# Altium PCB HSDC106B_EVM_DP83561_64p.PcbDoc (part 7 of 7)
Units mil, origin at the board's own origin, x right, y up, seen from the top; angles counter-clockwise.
Board outline 8750.24 x 6394.7 mil, 6 copper layers (Top Layer, GND1, SIG1, SIG2, GND2, Bottom Layer), stack 60.4 mil thick; 472 components, 324 nets, 1622 pads, 1086 vias.
Unrouted connection lines stored in the file: 1.
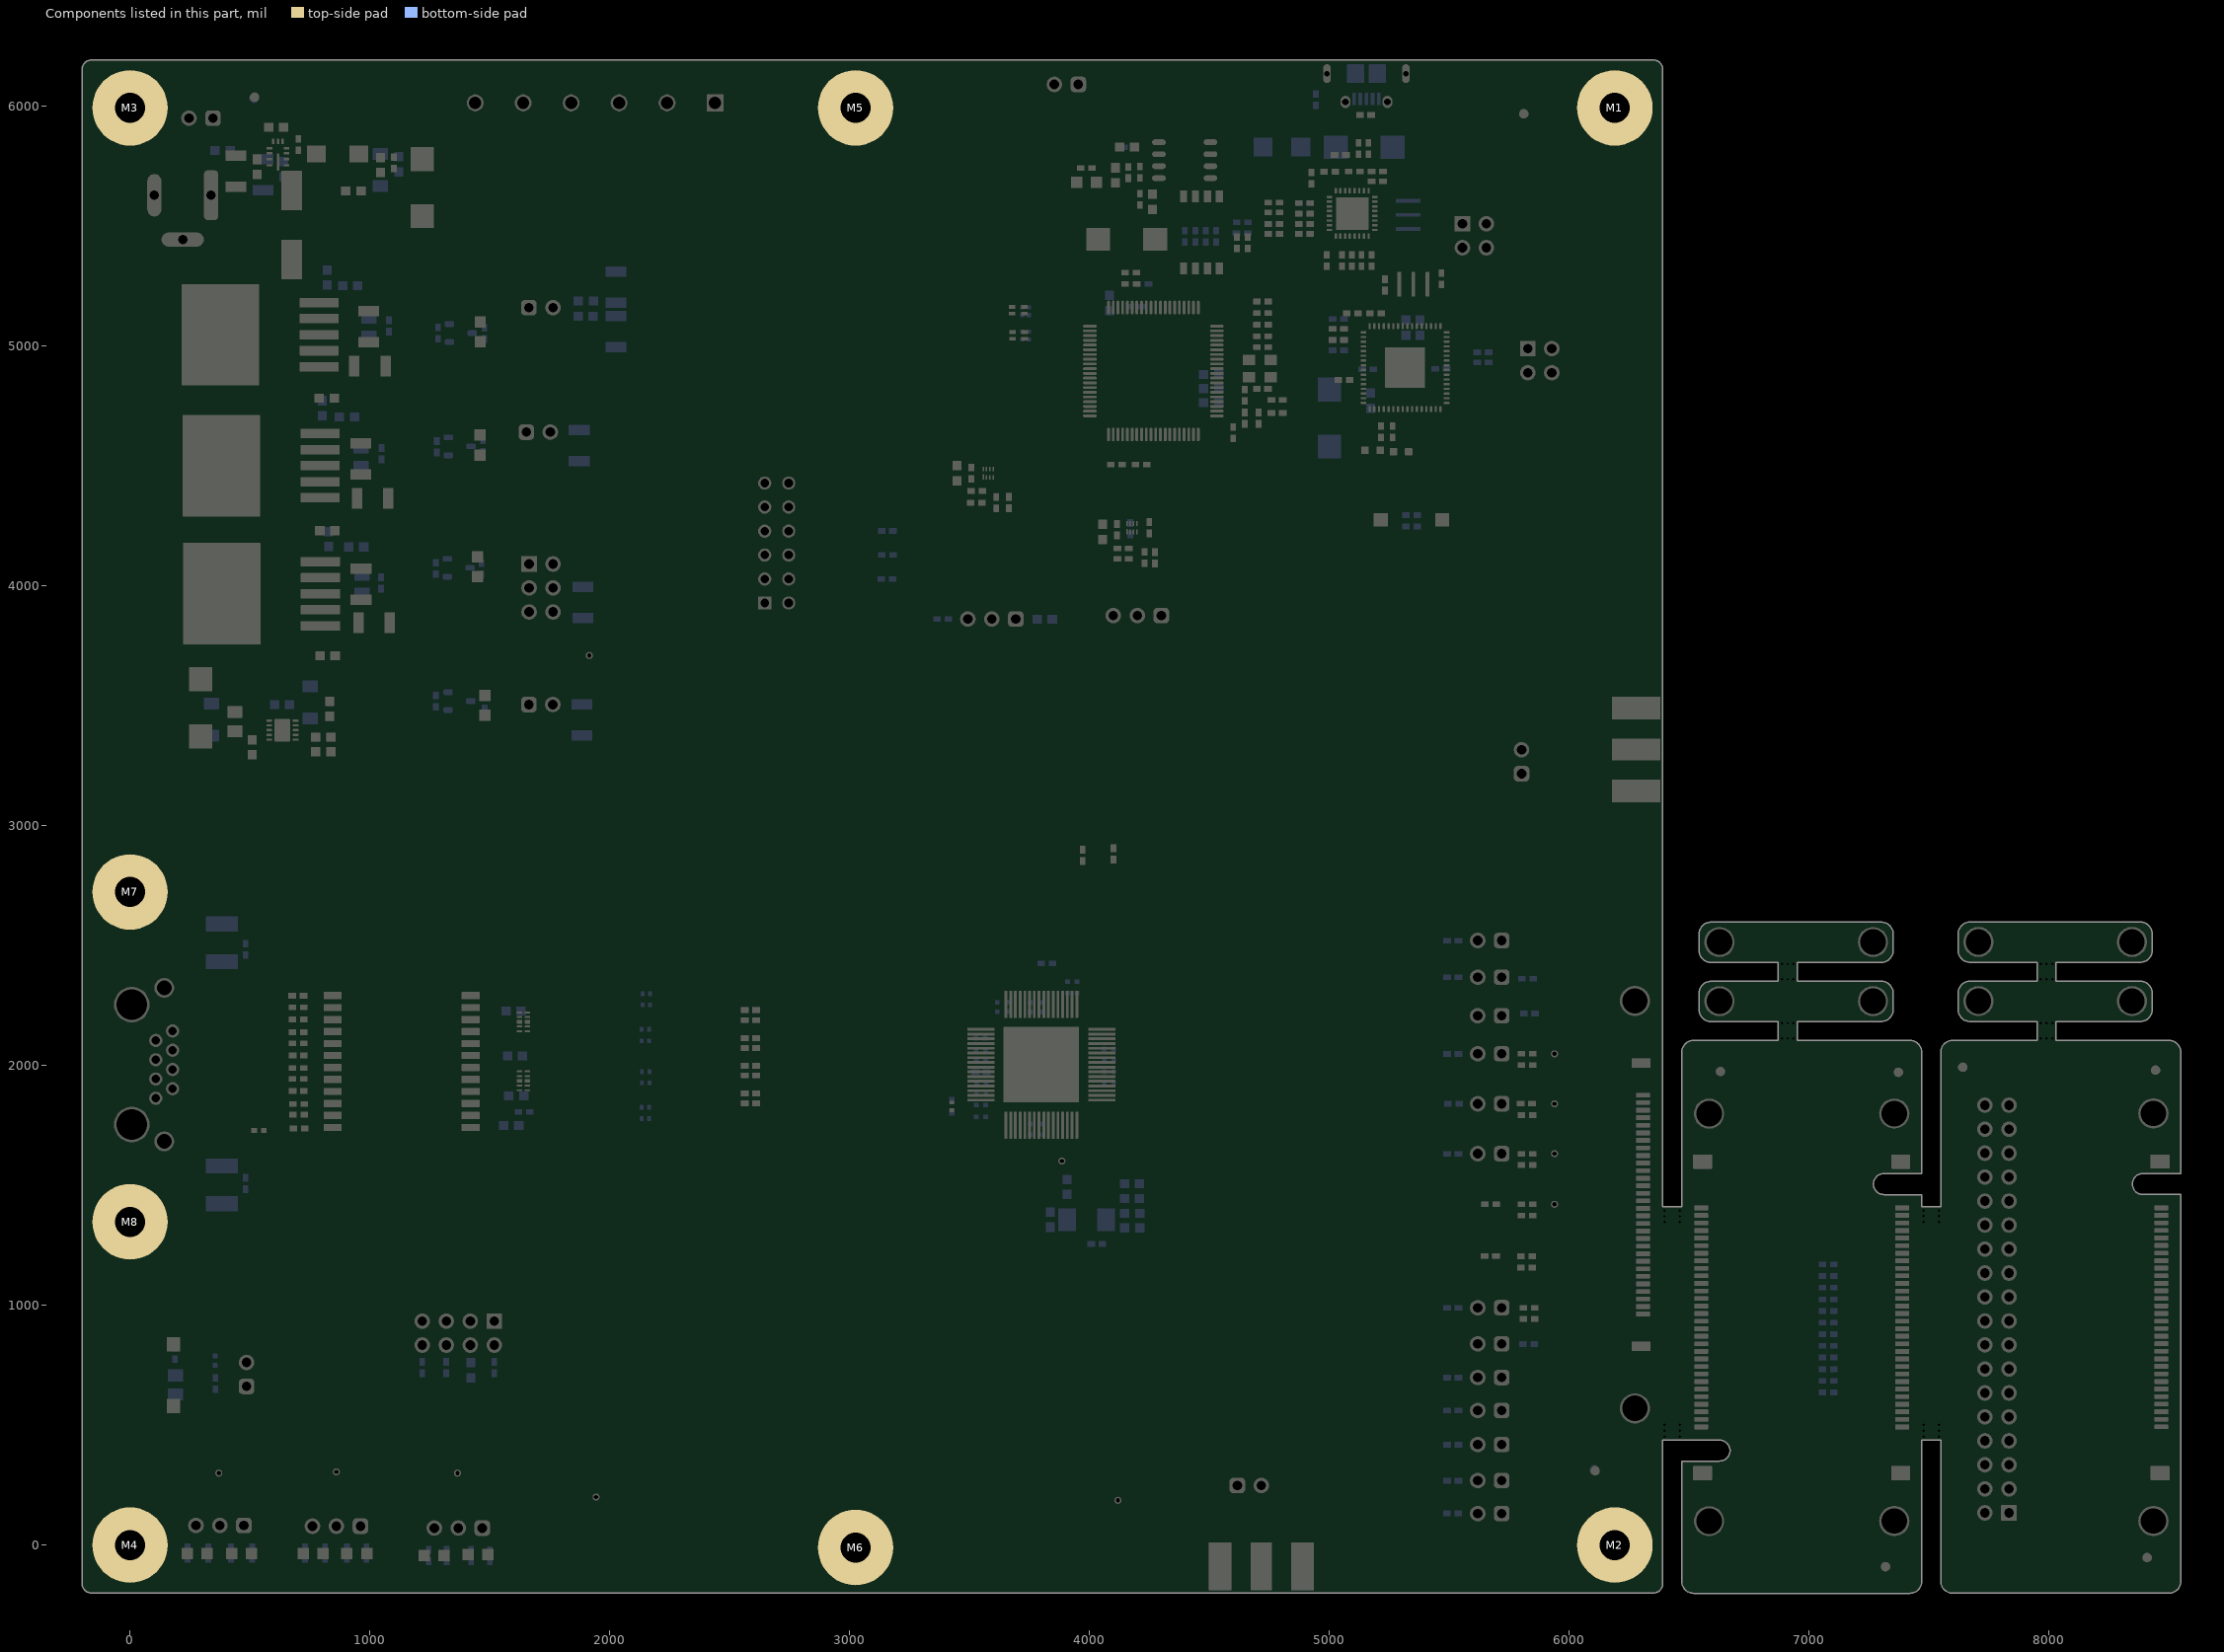
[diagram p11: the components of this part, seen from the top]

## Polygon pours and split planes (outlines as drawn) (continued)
VDDA2P5 on SIG2 "Bottom Layer-No Net" (solid, remove dead copper, pour order 795): 1990,5696.7 1844,5550.7 1844,4378.7 1820,4353.7 1528,4353.7 1492,4389.7 1492,5682.7 1706,5896.7 1706,6118.7 1721,6133.7 1972,6133.7 1990,6115.7
USB_VBUS on SIG2 "Bottom Layer-No Net" (solid, remove dead copper, pour order 798): 30 vertices, not listed, extent 3924,4404.7 6121.52,6171.7
GND_2 on SIG2 "GND_2" (solid, remove dead copper, pour order 821): 27 vertices, not listed, extent 6502,-169 7453,2087
RJ45_ERTH on SIG2 "Bottom Layer-No Net" (solid, remove dead copper, pour order 824): -160,1186.2 -115.4,1141.61 111.6,1141.61 187.6,1217.61 187.6,1490.61 213.6,1517.35 480.62,1517.35 529,1565.73 529,1621.64 529,2418.64 485.36,2462.28 -110.72,2462.28 -160,2413
GND_1 on SIG2 "GND_2" (solid, remove dead copper, pour order 817): 17 vertices, not listed, extent 7582,-160 8512,2066
VDDIO on SIG2 "Bottom Layer-No Net" (solid, pour order 789): 17 vertices, not listed, extent 982,3762.96 1823.64,6134.7
VDDA1P8_AB on SIG2 "Bottom Layer-No Net" (solid, remove dead copper, pour order 801): 17 vertices, not listed, extent 2678.8,1748.74 3639.99,5115.17
VDD1P0 on SIG2 "Bottom Layer-No Net" (solid, remove dead copper, pour order 796): 20 vertices, not listed, extent 1726,3382.2 2337.17,6138.7
VDDA2P5 on SIG2 "Bottom Layer-No Net" (solid, remove dead copper, pour order 799): 19 vertices, not listed, extent 2375.83,1889.05 3465.35,4561.03
1V8 on SIG1 "Bottom Layer-No Net" (solid, pour order 790): 19 vertices, not listed, extent 946.61,4043.7 1922,5306.7
VDD1P0 on SIG1 "VDD1P0_L03_P802" (solid, remove dead copper, pour order 802): 22 vertices, not listed, extent 1728.77,1914.64 4279,3546.97
OC_N on SIG1 "Bottom Layer-No Net" (solid, remove dead copper, pour order 797): 4908,5349.7 4908,5616.7 4919.5,5631.2 4932,5643.7 4992,5643.7 5016,5619.7 5016,5467.7 5036,5447.7 5131,5447.7 5144.81,5433.89 5144.81,5366.51 5099,5320.7 4937,5320.7
GND_2 on SIG1 "GND_2" (solid, remove dead copper, pour order 820): 27 vertices, not listed, extent 6502,-169 7453,2087
RJ45_ERTH on SIG1 "Bottom Layer-No Net" (solid, remove dead copper, pour order 825): -160,1186.2 -115.4,1141.61 111.6,1141.61 187.6,1217.61 187.6,1490.61 213.6,1517.35 480.62,1517.35 529,1565.73 529,1621.64 529,2418.64 485.36,2462.28 -110.72,2462.28 -160,2413
GND_1 on SIG1 "GND_2" (solid, remove dead copper, pour order 816): 17 vertices, not listed, extent 7582,-160 8512,2066
5V on SIG1 "Bottom Layer-No Net" (solid, pour order 793): 25 vertices, not listed, extent -169,3262.7 3895,6138.7
GND on SIG1 "Bottom Layer-No Net" (solid, remove dead copper, pour order 794): 5409,6174.7 5448,6135.7 5448,5757.7 5428,5737.7 4086,5737.7 4073,5750.7 4073,6168.7 4079,6174.7
1V1 on SIG1 "Bottom Layer-No Net" (solid, pour order 792): 852,3567.7 1361,3567.7 1394,3534.7 1693,3534.7 1701,3526.7 1701,3363.7 1689,3351.7 848,3351.7 839,3360.7 839,3554.7
3V3 on SIG1 "Bottom Layer-No Net" (solid, pour order 791): 17 vertices, not listed, extent 991,3592.7 1714,5110.7
GND on GND1 "GND_L02_P837" (solid, remove dead copper, pour order 837): 22 vertices, not listed, extent -160,-150.65 6359,6157.78
GND_2 on GND1 "GND_2" (solid, remove dead copper, pour order 819): 27 vertices, not listed, extent 6502,-169 7453,2087
RJ45_ERTH on GND1 "Bottom Layer-No Net" (solid, remove dead copper, pour order 826): -160,1186.2 -115.4,1141.61 111.6,1141.61 187.6,1217.61 187.6,1490.61 213.6,1517.35 480.62,1517.35 529,1565.73 529,1621.64 529,2418.64 485.36,2462.28 -110.72,2462.28 -160,2413
GND_1 on GND1 "GND_2" (solid, remove dead copper, pour order 815): 17 vertices, not listed, extent 7582,-160 8512,2066
GND on GND2 "GND_L05_P836" (solid, remove dead copper, pour order 836): 22 vertices, not listed, extent -160,-150.65 6359,6157.78
GND_2 on GND2 "GND_2" (solid, remove dead copper, pour order 822): 27 vertices, not listed, extent 6502,-169 7453,2087
RJ45_ERTH on GND2 "Bottom Layer-No Net" (solid, remove dead copper, pour order 823): -160,1186.2 -115.4,1141.61 111.6,1141.61 187.6,1217.61 187.6,1490.61 213.6,1517.35 480.62,1517.35 529,1565.73 529,1621.64 529,2418.64 485.36,2462.28 -110.72,2462.28 -160,2413
GND_1 on GND2 "GND_2" (solid, remove dead copper, pour order 818): 17 vertices, not listed, extent 7582,-160 8512,2066

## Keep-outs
Top Layer:
  circle w10: c5811,5969 r42.8
  circle w10: c6108.36,310.06 r42.8
  circle w10: c519,6038.7 r42.8
Keep-Out Layer:
  text ".Layer_Name" at 397,-2173.3 h60

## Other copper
Top Layer:
  pour cut-out: 3713.06,1326.61 3928.07,1326.61 ccw(c3928.07,1405.13) 3983.6,1349.61 3839.23,1493.98 ccw(c3784.6,1439.35) 3784.6,1516.61 3716.91,1516.61 cw(c3716.91,1543.92) 3697.6,1524.61
  pour cut-out: 1771.36,2180.29 1764.25,2173.17 1764.25,2154.8 1793.91,2125.14 1797.71,2128.93 1797.71,2180.29 1789.06,2188.94
  pour cut-out: 4141.65,4584.91 4196.09,4584.91 4217,4564 4217,4349.97 4282,4284.97 4282,4217 4334,4165 4334,3966 4262,3894 4262,3856 4230,3824 4230,3114 4158,3042 4158,2985.59 4138,2965.59 4138,2722 3877.73,2461.73 3868.46,2461.73 3818,2512.19 3818,2905 4068,3155 4068,3907.4 4162.25,4001.65 4162.25,4278.75 4139,4302 4139,4455 4111,4483 4111,4554.26
  pour cut-out: 4677,309 4747.68,309 4766.6,290.08 4766.6,214.74 4766.6,47.4 4795,19 4795,-180 4781,-194 4651,-194 4638,-181 4638,26 4668.71,56.71 4668.71,277 4668.71,300.71
  pour cut-out: 3323.84,2190.41 3345.4,2168.85 3345.4,2006.15 3359.95,1991.61 3366.82,1991.61 3366.82,2174.48 3357.6,2183.7
  pour cut-out: 5050,5773.7 5101,5773.7 5107,5767.7 5107,5708.05 5099.65,5700.7 5048,5700.7 5040,5708.7 5040,5763.7
  pour cut-out: 809.11,1671 1453.08,1671 1453.08,2366.7 809.11,2366.7
  pour cut-out: 1307.65,4563.7 1562.61,4563.31 1572,4572.7 1572,4645.7 1549,4668.7 1335,4668.7 1303,4636.7 1303,4567.48
  pour cut-out: 1269,5071.31 1291.61,5048.7 1551,5048.7 1575,5072.7 1575,5084.35 1508.67,5150.67 1421.97,5150.67 1420,5148.7 1335,5148.7 1269,5082.7
  pour cut-out: 4658,4730.7 4692,4730.7 4694,4728.7 4694,4653.7 4692,4651.7 4661.88,4651.7 4661.13,4652.46 4661.13,4706.57 4656,4711.7 4656,4728.7
  pour cut-out: 5025.09,5093.39 5024.27,5094.2 5002.5,5094.2 4994.97,5101.73 4994.97,5121.54 5048.76,5121.54 5048.76,5174.43 5063.56,5189.24 5182.15,5189.24 5195,5176.39 5195,5077.7 5188.25,5070.95 5037.75,5070.95 5025.09,5083.61
  pour cut-out: 5195,5121.11 5231.41,5121.11 5234,5123.7 5234,5151.7 5233.3,5152.4 5233.3,5167 5252.7,5167 5267.29,5152.41 5267.29,5099.99 5263,5095.7 5199,5095.7 5195,5099.7
  pour cut-out: 5070.42,4905.7 5062,4905.7 5053,4896.7 5053,4797.7 5058,4792.7 5096.39,4792.7 5097.59,4793.9 5097.59,4807.55 5107.75,4817.7 5125,4817.7 5128,4820.7 5128,4913.39 5120.15,4921.24 5081.4,4921.24 5070.42,4910.26
  pour cut-out: 5052,5627.7 5164.02,5627.7 5166.81,5624.91 5166.81,5561.18 5177.26,5550.73 5198.41,5550.73 5205.48,5543.66 5205.48,5515.18 5201,5510.7 5172.44,5510.7 5169.96,5508.23 5169.96,5484.61 5167.07,5481.71 5025.93,5481.71 5025.93,5622.34 5023.36,5624.91 5026.15,5627.7 5040,5627.7 5040,5634.37 5038.38,5635.99 5024.29,5635.99 5014,5625.7 5014,5480.7 5025,5469.7 5179.21,5469.7 5179.21,5493.61 5189.9,5504.29 5212.59,5504.29 5217,5508.7 5217,5550.7 5204.35,5563.35 5189.9,5563.35 5177.89,5575.35 5177.89,5589.81 5172.86,5589.86
  pour cut-out: 4922.09,5444.74 4922.09,5376.03 4923.63,5374.49 4961.21,5374.49 4986.21,5349.49 5205.83,5349.49 5206.83,5350.49 5206.83,5397.49 5227.83,5418.49 5227.83,5447.49 5203.77,5471.55 5179.11,5471.55 5166.36,5458.8 5024.34,5458.8 5024.34,5458.98 5006.83,5476.49 4953.83,5476.49
  region net VDD1P0: 3909.23,2370.53 3931.19,2370.53 3965.01,2404.35 3965.01,2411.94 3952.86,2424.09 3935.3,2424.09 3902.6,2391.39 3902.6,2377.16
  region net VDDA2P5: 3403.02,1952.01 3446.02,1952.01 3457.32,1940.7 3457.32,1934.57 3450.67,1927.92 3405.03,1927.92 3398.25,1934.7 3398.25,1947.24
  region net VDD1P0: 3411.25,2031.01 3456.02,2031.01 3467.32,2019.7 3467.32,2013.57 3460.67,2006.92 3409.62,2006.92 3403.86,2012.68 3403.86,2023.62
  region net VDDA2P5: 3426.3,2082.22 3434.89,2082.22 3449.47,2096.8 3406.71,2139.56 3397.3,2139.56 3387.82,2130.07 3387.82,2120.38
  pour cut-out: 2858.29,3250.71 3561,2548 3821.9,2548 3951.01,2677.11 3942.03,2686.09 3942.03,2992.82 3829.99,3104.86 3149.95,3784.9 3149.95,4001 2806,4351 2806,4490 2670.95,4490 2573.73,4490 2573.73,3858.47 2858.29,3859.5
  pour cut-out: 3388.85,2385.97 3570.74,2567.86 3580.58,2567.86 3597.83,2550.61 3470.56,2423.34 3470.56,2239.69 3431.16,2200.3 3388.85,2242.61
  pour cut-out: 3613.6,2192.09 3613.6,1817.84 3986.64,1817.84 3986.64,2188.61
  text ".Layer_Name" at 480,-2173.79 h60
GND1:
  pour cut-out: 804.45,1672 1454.36,1672 1454.36,2369 804.45,2369
  text ".Layer_Name" at 480,-2173.79 h60
SIG1:
  pour cut-out: 804.45,1672 1454.12,1672 1454.12,2368 804.45,2368
  text ".Layer_Name" at 480,-2173.79 h60
SIG2:
  pour cut-out: 799,1724 1460.36,1724 1460.36,2319 799,2319
  pour cut-out: 804,1671 1462.84,1671 1462.84,2371 804,2371
  text ".Layer_Name" at 480,-2173.79 h60
GND2:
  pour cut-out: 807,1671 1460.36,1671 1460.36,2368 807,2368
  text ".Layer_Name" at 480,-2173.79 h60
Bottom Layer:
  pour cut-out: 2714,4263 3151,4263 3151,3995.44 3150.44,3996 2714,3996
  pour cut-out: 3150,4243
  pour cut-out: 4748.59,2703.59 5408,3363 6375,3363 6380,3358 6380,3280 6373,3273 5406,3273 4845,2712 4845,2706.59 4848,2703.59 5675.62,2703.59 6134.17,2245.03 6262,2117.2 6262,1046 5830.28,614.28 5830.28,238.54 5737.74,146 4911,146 3792,1265 3792,1471.07 3949.63,1628.69 3949.63,1940.12 3966.64,1957.13 3966.64,2193.54 3927.2,2232.98 3927.2,2402.4 4048.15,2523.36 4529.58,2523.36 4709.81,2703.59
  pour cut-out: 5215,5478.15 5258.85,5522 5386.15,5522 5400,5508.15 5400,5465 5390,5455 5272.17,5455 5261.42,5444.25 5220.9,5444.25 5215,5450.15
  pour cut-out: 5215,5597 5256,5638 5391,5638 5400,5629 5400,5587.59 5387.41,5575 5273.32,5575 5261.42,5563.1 5220.9,5563.1 5215,5569
  pour cut-out: 2103.23,2321.42
  pour cut-out: 3381.6,2170.61 3381.6,1942.46 3428.45,1895.61 3585.6,1895.61 3593.6,1903.61 3593.6,1942.92 3550.6,1985.92 3550.6,2059.61 3524.6,2085.61 3524.6,2171.01 3519,2176.61 3388.6,2176.61 3382.6,2170.61
  pour cut-out: 1222.69,5.97 1222.69,-127.39 1478.6,-127.39 1478.6,23.98
  pour cut-out: 442.6,46.98 219.11,46.98 219.11,-114.39 389.52,-114.39 389.52,15.97 398.69,15.97
  pour cut-out: 707.69,15.97 707.69,-114.39 922.6,-114.39 922.6,18.61
  pour cut-out: 476,3434.7 476,3337.7 480,3333.7 549.84,3333.7 578.84,3362.7 593,3362.7 598,3367.7 598,3384.7 591,3391.7 591,3468.7 578.62,3481.08 521.38,3481.08 475,3434.7
  pour cut-out: 1376,4166.7 1381,4161.7 1381,4066.7 1374,4059.7 1318,4059.7 1297,4080.7 1297,4159.2 1304.5,4166.7
  pour cut-out: 1331,4673.7 1377,4673.7 1389,4661.7 1389,4579.7 1370,4560.7 1370,4559.7 1319.24,4559.7 1317.62,4558.08 1309,4566.7 1309,4660.7 1321,4672.7 1331,4672.7
  pour cut-out: 1330,5148.7 1382,5148.7 1391,5139.7 1391,5043.7 1382,5034.7 1321,5034.7 1307,5048.7 1307,5131.54 1327.18,5151.72
  pour cut-out: 1454.36,2369 806,2369 806,1671 1454.36,1671
  pour cut-out: 4331.37,2758.63 4164,2926 4041.95,2926 3986,2981.95 3986,3014 4021,3049 4371,3049 4787.17,2632.83 5866.17,2632.83 6244,2255 6244,1005 6024.6,785.6 5706.07,785.6 5701.35,784.73 5667.06,819.02 5085.52,819.02 4402.35,1502.2 4055.84,1502.2 4033.17,1524.87 4033.17,1678.05 4033.17,1787.17 4140,1894 4409,1894 4460.42,1945.42 4460.42,2036.44 4448.56,2048.3 4400.63,2048.3 4400.63,2035.17 4346.26,1980.8 4331.37,1995.69
  text ".Layer_Name" at 558,-2173.79 h60

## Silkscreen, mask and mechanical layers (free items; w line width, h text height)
Top Overlay:
  drawing of 165 lines, arcs and shapes, not listed
  text "USB_VBUS" at 4020,6074 h60
  text "5V" at 3720,6070 h40
  text "GND" at 189.97,6022.65 h40
  text "5V" at 335.97,6016.65 h40
  text "5V" at 2471.6,5737.61 h40 r90
  text "GND" at 1465,5713 h40 r90
  text "VDD1P1" at 2240.6,5626.61 h40 r90
  text "VDDIO" at 1672.6,5622.61 h40 r90
  text "EZFET_RST" at 5493,5579 h30
  text "VDDA1P8" at 2035.6,5575.61 h40 r90
  text "VDDA2P5" at 1860.6,5550.7 h40 r90
  text "5V" at 408,5547 h40
  text "GND" at 5724.97,5487.96 h40
  text "GND" at 5722,5386 h40
  text "EZFET_TST" at 5505,5306.61 h30
  text "MSP_TST" at 5758,5063 h40
  text "1V8" at 1574,5050 h40
  text "VDDA1P8" at 1719.6,5045.61 h40
  text "1V8" at 61,5034 h40
  text "GND" at 6003.78,4962.25 h40
  text "GND" at 6009.78,4857.25 h40
  text "MSP_RST" at 5770.78,4777.25 h40
  text "2V5" at 58.95,4539.7 h40
  text "2V5" at 1582,4519 h40
  text "VDDA2P5" at 1750,4518 h40
  text "MSP Reset" at 5202,4385 h40
  text "1V8" at 1495,4069.7 h40
  text "2V5" at 1496,3976.7 h40
  text "3V3" at 56,3969 h40
  text "INT_PWDN" at 3467,3941 h30
  text "VDDIO" at 1884,3898 h40 r90
  text "3V3" at 1497,3882.7 h40
  text "MDC" at 4030,3783 h30
  text "GND" at 4301,3783 h30
  text "MDIO" at 4152,3779 h30
  text "1V1" at 61,3496 h40
  text "1V1" at 1604,3410 h30
  text "VDD1P1" at 1716,3401 h40
  text "CLKOUT" at 5887,3305 h35
  text "GND" at 5883,3186 h40
  text "PU" at 5572,2590 h25
  text "SMI_DISABLE" at 5787,2505 h35
  text "PU" at 5569,2431 h25
  text "CRS (MII/RGMII)" at 5785,2364 h35
  text "GND" at 5466,2195 h25
  text "COL" at 5815,2190 h35
  text "PU" at 5571,2114 h25
  text "GND" at 5977,2029 h40
  text "RX_CTRL (MIRROR_EN)" at 4901,2012 h35
  text "MAC interface breakout" at 7774,1983 h60
  text "PU" at 5567.6,1904.01 h25
  text "RX_D3 (OPMODE_1)" at 5003,1828 h35
  text "RX_ER_1" at 7906,1824 h30
  text "GND" at 5977,1823 h40
  text "MDIO_1" at 7904,1719 h30
  text "PU" at 5565.6,1699.61 h25
  text "MDC_1" at 7909,1624 h30
  text "RX_D2 (OPMODE_2)" at 4992,1616 h35
  text "GND" at 5978,1612 h40
  text "GTX_CLK_1" at 7909,1525 h30
  text "DP83561EVM" at 799,1444 h100
  text "RX_CLK_1" at 7908,1424 h30
  text "GND" at 5974,1402 h40
  text "RX_D1 (PHY_ADD[3:2])" at 4869,1385 h35
  text "TX_D0_1" at 7909,1322 h30
  text "HSDC106E1" at 869,1220 h100
  text "RX_D0_1" at 7909,1218 h30
  text "RX_D0 (PHY_ADD[1:0])" at 4859,1168 h35
  text "TX_D1_1" at 7907,1115 h30
  text "PU" at 5579,1060 h25
  text "RX_D1_1" at 7912.47,1025.08 h30
  text "GND" at 1311.77,1000.41 h35
  text "GND_1" at 7653,1001 h40 r90
  text "RX_CLK" at 5334,981 h35
  text "TX_D2_1" at 7904.47,920.08 h30
  text "RESET_N" at 140,917 h35
  text "RX_D2_1" at 7908.47,823.08 h30
  text "GND" at 5465,809 h25
  text "RX_ER" at 5814,804 h35
  text "RESET_N" at 561,743 h30
  text "TX_D3_1" at 7911.47,718.08 h30
  text "AUTO_RECOVER" at 5120,685 h35
  text "GND" at 555,633 h30
  text "RX_D3_1" at 7912.47,618.08 h30
  text "JTAG_TDO (OPMODE_0)" at 4893,543 h35
  text "JTAG_TDI" at 1225.6,516.61 h35 r90
  text "TX_CTRL_1" at 7915.47,517.08 h30
  text "JTAG_CLK" at 1432.56,499.61 h35 r90
  text "JTAG_TMS" at 1529.25,493.41 h35 r90
  text "JTAG_TDO" at 1325.88,493.05 h35 r90
  text "RX_CTRL_1" at 7931.47,417.08 h30
  text "SUPPLY MODE (TRIPLE/DUAL)" at 4685,403 h35
  text "ANEGSEL_1" at 223,401 h35
  text "ANEGSEL_0" at 728,401 h35
  text "ANEG_DIS" at 1223.6,391.61 h35
  text "RESETN_1" at 7916.47,321.08 h30
  text "GND" at 898,289 h40
  text "GND" at 1416,284 h40
  text "GND" at 405,282 h40
  text "GND" at 1886,244 h40
  text "CRS_1" at 7922.47,226.08 h30
  text "VDDIOSEL_0" at 5790,193 h35
  text "GND" at 4417,178 h40
  text "PU LED0 PD" at 1215,149 h35
  text "PU LED2 PD" at 204,146 h35
  text "PU LED1 PD" at 705,146 h35
  text "EXT_REF_CLK" at 4603,124 h35
  text "COL_1" at 7913.47,119.08 h30
  text "VDDIOSEL_1" at 5644,20 h35
  text "RGMII back-to-back connector" at 6488,-116 h60
  text ".Layer_Name" at 464,-2173.79 h60
Bottom Overlay:
  circle w10: c4100.65,1273.65 r2
  circle w10: c705,3446.77 r2
  circle w10: c1317,3451 r2
  circle w10: c1319,4003 r2
  circle w10: c1320,4508 r2
  circle w10: c1319,4975 r2
  circle w10: c485,5777 r2
  circle w10: c978,5806 r2
  circle w6: c5419,5610 r10.48
  circle w7: c5104.6,5984.61 r7.69
  lines w6: 3473,2127 3473,1364 3481,1356 3592,1356 3603,1367 3603,1438
  text ".Layer_Name" at 480,-2173.79 h60
Top Paste:
  text ".Layer_Name" at 377,-2173.79 h60
Bottom Paste:
  text ".Layer_Name" at 377,-2193.79 h60
Top Solder:
  text ".Layer_Name" at 377,-2173.79 h60
  text ".Layer_Name" at 377,-2173.79 h60
Bottom Solder:
  text ".Layer_Name" at 377,-2193.79 h60
Drill Guide:
  text ".Layer_Name" at 395,-2170.3 h60
M1 Board Outline:
  lines w10: 6390.55,437.61 6390.55,-160 cw(c6350.55,-160) 6350.55,-200 -160,-200 cw(c-160,-160) -200,-160 -200,6153.7 cw(c-160,6153.7) -160,6193.7 6350.55,6193.7 cw(c6350.55,6153.7) 6390.55,6153.7 6390.55,1410.43 ; 6390.55,516.54 6390.55,860.94 6236.02,860.94 cw(c6235.46,893.9) 6202.5,893.34 cw(c6236.53,893.85) 6236.02,927.87 6390.55,927.87 6390.55,1331.61 ; 6390.84,516.54 6468.58,516.54 6469.29,1173.2 6469.29,1318.87 6469.29,1331.69 ; 6390.84,1331.69 6468.29,1331.69 ; 6390.84,1410.43 6468.29,1410.43 ; 6391.84,437.8 6469.58,437.8 6627.15,437.8 cw(c6627.15,394.35) 6670.6,394.35 6670.6,393.93 cw(c6627.06,393.93) 6627.06,350.39 6469.58,350.39 6469.29,297.49 ; 6469.29,296.2 6469.29,-151 ccw(c6519.29,-151) 6519.29,-201 7420.39,-201 ccw(c7420.39,-151) 7470.39,-151 7470.39,200.76 7470.39,346.43 7470.39,438.1 ; 6469.29,1410.43 6469.29,2054.61 cw(c6519.29,2054.61) 6519.29,2104.61 6871.81,2104.61 6871.81,2183.35 6591.84,2183.35 cw(c6591.84,2233.35) 6541.84,2233.35 6541.84,2301.35 cw(c6591.84,2301.35) 6591.84,2351.35 6871.81,2351.35 6871.81,2430.09 6591.84,2430.09 cw(c6591.84,2480.09) 6541.84,2480.09 6541.84,2548.09 cw(c6591.84,2548.09) 6591.84,2598.09 7301,2598.09 ; 7301,2351.35 6950.55,2351.35 6950.55,2430.09 7301.13,2430.09 ; 7301.13,2183.35 6950.55,2183.35 6950.55,2104.61 7420.39,2104.61 cw(c7420.39,2054.61) 7470.39,2054.61 7470.39,1549.13 ; 7301.13,2183.47 ccw(c7301.13,2233.47) 7351.13,2233.47 7351.13,2301.47 ccw(c7301.13,2301.47) 7301.13,2351.47 ; 7301.13,2430.21 ccw(c7301.13,2480.21) 7351.13,2480.21 7351.13,2548.21 ccw(c7301.13,2548.21) 7301.13,2598.21 ; 7469.7,1461.72 7312.13,1461.72 cw(c7312.13,1505.17) 7268.68,1505.17 7268.68,1505.59 cw(c7312.22,1505.59) 7312.22,1549.13 7469.7,1549.13 ; 7470.39,516.84 7470.39,1144.69 7470.39,1223.43 7470.39,1327.61 ; 7470.39,1410.74 7470.39,1461.72 ; 7470.68,516.84 7548.42,516.84 7549.13,1173.5 7549.13,1319.17 7549.13,1332 ; 7470.68,1332 7548.13,1332 ; 7470.68,1410.74 7548.13,1410.74 ; 7471.68,438.1 7549.42,438.1 7549.42,350.7 7549.13,297.8 ; 7549.13,296.5 7549.13,-150.69 ccw(c7599.13,-150.69) 7599.13,-200.69 8500.24,-200.69 ccw(c8500.24,-150.69) 8550.24,-150.69 8550.24,201.06 8550.24,346.73 8550.24,1144.99 8550.24,1223.73 8550.24,1462.03 ; 7549.13,1410.74 7549.13,2054.91 cw(c7599.13,2054.91) 7599.13,2104.91 7951.65,2104.91 7951.65,2183.65 7671.68,2183.65 cw(c7671.68,2233.65) 7621.68,2233.65 7621.68,2301.65 cw(c7671.68,2301.65) 7671.68,2351.65 7951.65,2351.65 7951.65,2430.39 7671.68,2430.39 cw(c7671.68,2480.39) 7621.68,2480.39 7621.68,2548.39 cw(c7671.68,2548.39) 7671.68,2598.39 7951.65,2598.39 8030.39,2598.39 8380.84,2598.39 ; 8380.84,2351.65 8030.39,2351.65 8030.39,2430.39 8380.97,2430.39 ; 8380.97,2183.65 8030.39,2183.65 8030.39,2104.91 8500.24,2104.91 cw(c8500.24,2054.91) 8550.24,2054.91 8550.24,1549.43 ; 8380.97,2183.78 ccw(c8380.97,2233.78) 8430.97,2233.78 8430.97,2301.78 ccw(c8380.97,2301.78) 8380.97,2351.78 ; 8380.97,2430.52 ccw(c8380.97,2480.52) 8430.97,2480.52 8430.97,2548.52 ccw(c8380.97,2548.52) 8380.97,2598.52 ; 8549.54,1462.03 8391.97,1462.03 cw(c8391.97,1505.48) 8348.52,1505.48 ; 8549.54,1549.43 8392.06,1549.43 ccw(c8392.06,1505.89) 8348.52,1505.89 ; 8348.52,1505.48 8348.52,1505.89 ; 8348.52,1505.48 8348.52,1505.89
  text ".layer_name" at 405,-2183.79 h60
M2 Board Dimensions:
  rectangle: -75,-1715.3 300,-1590.3
  rectangle: -200,-1590.3 -75,-1465.3
  lines w7: -200,-1590.3 800,-1590.3 ; -75,-1715.3 -75,-1465.3 ; 50,-1715.3 50,-1465.3 ; 300,-1715.3 300,-1465.3 ; 550,-1715.3 550,-1465.3 ; -200,-1715.3 -200,-1465.3 800,-1465.3 800,-1715.3 -200,-1715.3
M3 3D STEP Top:
  text ".Layer_Name" at 377,-2173.79 h60
M4 3D STEP Bottom:
  text ".Layer_Name" at 377,-2193.79 h60
M5 Assembly Top:
  circle w10: c8434,1442 r5.39
  circle w10: c7842,40 r5.39
  circle w10: c7363,1441 r5.39
  circle w10: c6260,945 r5.39
  circle w10: c6625,491 r5.39
  circle w10: c5795,140 r5.39
  circle w10: c5792,276 r5.39
  circle w10: c5795,434 r5.39
  circle w10: c5790,564 r5.39
  circle w10: c5791,698 r5.39
  circle w10: c5792,839 r5.39
  circle w10: c5795,1029 r5.39
  circle w10: c5791,1676 r5.39
  circle w10: c5797.98,1890.58 r5.39
  circle w10: c5801.34,2098.82 r5.39
  circle w10: c5791,2210 r5.39
  circle w10: c5795,2361 r5.39
  circle w10: c5801.83,2525.66 r5.39
  circle w10: c6122,3335 r5.39
  circle w10: c3460,2158 r5.39
  circle w10: c4599,323 r5.39
  circle w10: c4748.47,62.6 r5.39
  circle w10: c1557,67 r5.39
  circle w10: c1042,74 r5.39
  circle w10: c554.69,83.25 r5.39
  circle w10: c115,534 r5.39
  circle w10: c557,647 r5.39
  circle w10: c1618,937 r5.39
  circle w10: c1420,1694 r5.39
  circle w10: c99,1605 r5.39
  circle w10: c747.71,3771.14 r5.39
  circle w10: c731,4863 r5.39
  circle w10: c737,4304 r5.39
  circle w10: c5879,3193 r5.39
  circle w10: c1634,3596 r5.39
  circle w10: c1654,4182 r5.39
  circle w10: c1644,4721 r5.39
  circle w10: c1631,5243 r5.39
  circle w10: c3753,5021 r5.39
  circle w10: c3753,5128 r5.39
  circle w10: c3465,5176 r5.39
  circle w10: c3760.51,3852.97 r5.39
  circle w10: c4384,3867 r5.39
  circle w10: c5507,4336 r5.39
  circle w10: c5289,5196 r5.39
  circle w10: c4035,6085 r5.39
  circle w10: c766,5927 r5.39
  circle w10: c393,5587 r5.39
  circle w10: c416,5963 r5.39
  lines w6: 444,811.76 435.95,811.76 ; 679,5709 714,5709 ; 695,5693 695,5728 ; 435.95,811.76 435.95,611.76 535.95,611.76 535.95,811.76 435.95,811.76 ; 195.6,5900.61 195.6,6000.61 395.6,6000.61 395.6,5900.61 195.6,5900.61 ; 1602,4591.61 1602,4691.61 1802,4691.61 1802,4591.61 1602,4591.61 ; 4566.6,198.61 4566.6,298.61 4766.6,298.61 4766.6,198.61 4566.6,198.61 ; 5568.6,2257.61 5570.2,2256.01 5570.2,2159.2 5767,2159.2 5768.6,2157.61 5768.6,2257.61 5568.6,2257.61 ; 5568.99,789.65 5568.99,889.65 5768.99,889.65 5768.99,789.65 5568.99,789.65 ; 5751.67,3166.74 5751.67,3366.74 5851.67,3366.74 5851.67,3166.74 5751.67,3166.74
  lines w10: -492,-2245.47 6108,-2245.47 ; -492,-2042.13 6110,-2042.13 ; -492,-1838.8 -492,-2448.8 3513,-2448.8 6110,-2448.8 6110,-1838.8 -491.5,-1838.8 -491.5,-2448.8 1084,-2448.8 ; 1973,-2448.8 1973,-1838.8 ; 3240,-2042.13 3240,-1838.8 ; 4080,-2042.13 4080,-1838.8 ; 4702,-2455.3 4702,-2252.47 ; 6919,2755 6799,2635 6797,2635 ; 6797,2635 6831,2643 6797,2663 6797,2635
  text "4) SMALL STIRIPS AND MOUNTING HOLES ADDED IN DESIGN" at 6710.78,2931 h50
  text "THOSE ARE DESIGN REQUIREMENT. WHILE SHIPPING BOARDS, PLEASE HAND OVER TO CUSTOMER" at 6856.78,2843 h50
  text "STRIPS DESIGN REQUIREMENT" at 6931,2741 h50
  text "COMPONENTS MARKED 'DNP' SHOULD NOT BE POPULATED." at 2913.5,-1569.8 h60
  text "ASSEMBLY VARIANT:" at 2913,-1685.3 h60
  text ".VariantName" at 3949,-1685.3 h60
  text "PCB VIEWED FROM TOP SIDE" at -428.5,-1970.97 h60
  text "BOARD #:" at 2048,-1970.97 h60
  text "REV:" at 3438,-1970.97 h60
  text ".PCB_rev" at 3729.5,-1970.97 h60
  text "SVN REV:" at 4276,-1970.97 h60
  text ".VersionControl_RevNumber" at 4782,-1970.97 h60
  text ".PRJ_Number" at 2532,-1979.3 h50
  text "Layer Name:" at -393,-2158.01 h60
  text ".Layer_Name" at 480,-2173.79 h60
  text "NA" at 2466,-2173 h60
  text "TID #:" at 2048,-2174.3 h60
  text "PLOT NAME =" at -473,-2379 h50
  text ".plot_File_Name" at 81,-2379 h50
  text "GENERATED    :" at 2050,-2379.64 h60
  text ".Print_Date" at 2919.5,-2379.64 h60
  text ".Print_Time" at 3648.5,-2379.64 h60
  text "TEXAS INSTRUMENTS" at 4913,-2379.64 h60
M6 Assembly Bottom:
  circle w10: c4108,1271 r2.01
  circle w10: c1320,3446 r2.01
  circle w10: c1319,3995 r2.01
  circle w10: c1317.85,4498.13 r2.01
  circle w10: c1321,4967 r2.01
  circle w10: c5109.36,5980.98 r2.01
  lines w6: 1312,4644.7 1318,4644.7 1413,4644.7 1413,4606.7 ; 1315,5115.7 1331,5115.7 ; 1317,4520.7 1412,4520.7 1412,4557.7 ; 1361,4125.7 1412,4125.7 1412,4104.7 ; 1363,3566.7 1414,3566.7 1414,3545.7 ; 1368,4027.7 1411,4027.7 1411,4052.7 ; 1370,3468.7 1413,3468.7 1413,3493.7 ; 1417,5028.7 1417,4991.7 1322,4991.7 1315,4991.7 1315,4993.7 1315,5113.7 1317,5115.7 1323,5115.7 1418,5115.7 1418,5077.7
  lines w10: -492.5,-2042.63 6109.5,-2042.63 ; -490.5,-2245.97 6109.5,-2245.97 ; 915.5,-2455.8 915.5,-2252.97 ; 1537.5,-2042.63 1537.5,-1839.3 ; 2377.5,-2042.63 2377.5,-1839.3 ; 3644.5,-2449.3 3644.5,-1839.3 ; 4533.5,-2449.3 6109,-2449.3 6109,-1839.3 -492.5,-1839.3 -492.5,-2449.3 2104.5,-2449.3 6109.5,-2449.3 6109.5,-1839.3
  text "COMPONENTS MARKED 'DNP' SHOULD NOT BE POPULATED." at 5902,-1633.3 h60
  text ".VariantName" at 4858,-1749.3 h60
  text "ASSEMBLY VARIANT:" at 5897,-1749.3 h60
  text ".PRJ_Number" at 3061,-1967.47 h50
  text ".VersionControl_RevNumber" at 835.5,-1971.47 h60
  text "SVN REV:" at 1341.5,-1971.47 h60
  text ".PCB_rev" at 1888,-1971.47 h60
  text "REV:" at 2179.5,-1971.47 h60
  text "BOARD #:" at 3569.5,-1971.47 h60
  text "PCB VIEWED FROM BOTTOM SIDE" at 6046,-1971.47 h60
  text "Layer Name:" at 6022,-2165.01 h60
  text ".Layer_Name" at 5285,-2167 h60
  text "NA" at 3024,-2174.8 h60
  text "TID #:" at 3569.5,-2174.8 h60
  text "PLOT NAME =" at 6099,-2375 h50
  text ".plot_File_Name" at 5539,-2378 h50
  text "TEXAS INSTRUMENTS" at 704.5,-2380.14 h60
  text ".Print_Time" at 1969,-2380.14 h60
  text ".Print_Date" at 2698,-2380.14 h60
  text "GENERATED    :" at 3567.5,-2380.14 h60
M7 LPKF Text Top:
  text ".Layer_Name" at 480,-2173.79 h60
M8 LPKF Text Bottom:
  text ".Layer_Name" at 480,-2173.79 h60
M9 Title Sheet:
  drawing of 56 lines, arcs and shapes, not listed
  text "1" at 539.84,6721.2 h70
  text "2" at 3035.5,6721.2 h70
  text "3" at 5524.84,6721.2 h70
  text "5" at 10530.5,6721.2 h70
  text "6" at 13035.5,6721.2 h70
  text "A" at -616.5,5578.2 h70
  text "A" at 14183.5,5578.2 h70
  text "B" at -616.5,3198.2 h70
  text "B" at 14183.5,3198.2 h70
  text "C" at -616.5,823.2 h70
  text "C" at 14183.5,823.2 h70
  text "PROJECT TITLE:" at 11143.5,-1037.8 h45
  text ".prj_title" at 11193.5,-1171.13 h70
  text "DESIGNED FOR:" at 11143.5,-1338.8 h45
  text "TI" at 11193.5,-1478.8 h70
  text "D" at -616.5,-1546.8 h70
  text "D" at 14183.5,-1546.8 h70
  text "FILE NAME:" at 11143.5,-1638.8 h45
  text ".PCB_File_Name_No_Path" at 11193.5,-1758.8 h70
  text "Texas Instruments (TI) and/or its licensors do not warrant the accuracy or completeness of this specification" at 6174,-1920.64 h45
  text "ENGINEER:" at 11143.5,-1928.8 h45
  text "LAYOUT BY:" at 12648.5,-1928.8 h45
  text "or any information contained therein. TI and/or its licensors do not warrant that this design will meet" at 6129.01,-2033.3 h45
  text "Justin" at 11193.5,-2083.79 h70
  text "Tessolve" at 12699,-2083.79 h70
  text "the specifications, will be suitable for your application or fit for any particular purpose, or will operate in" at 6129.01,-2145.97 h45
  text "ALTIUM DESIGNER VERSION:" at 12648.5,-2238.8 h45
  text "an implementation. TI and/or its licensors do not warrant that the design is production worthy. You should" at 6129.01,-2258.63 h45
  text "completely validate and test your design implementation to confirm the system functionality for your application." at 6174,-2371.3 h45
  text ".print_Scale" at 11193.5,-2372.13 h70
  text ".Application_BuildNumber" at 12699,-2372.13 h70
  text "1" at 539.84,-2578.8 h70
  text "2" at 3035.5,-2578.8 h70
  text "3" at 5524.84,-2578.8 h70
  text "4" at 8031.51,-2578.8 h70
  text "5" at 10530.5,-2578.8 h70
  text "6" at 13035.5,-2578.8 h70
M10 Fab Notes:
  drawing of 193 lines, arcs and shapes, not listed
  text "DESIGN INFORMATION" at 12181.02,4594.7 h60
  text "MIN. TRACK WIDTH:" at 11536.46,4414.7 h60
  text "6" at 12632.7,4414.7 h60
  text "MIL" at 12787.46,4414.7 h60
  text "MIN. CLEARANCE:" at 11536.46,4282.7 h60
  text "MIL" at 12787.46,4282.7 h60
  text "4.6" at 12568,4281 h60
  text "18" at 12600.6,4151.61 h60
  text "MIN. VIA PAD SIZE:" at 11536.46,4150.7 h60
  text "MIL" at 12787.46,4150.7 h60
  text "FAB NOTES:" at 6557.6,4030.61 h50
  text "0.127mm (5MIL)" at 12231.46,4008.99 h60
  text "MINIMUM ANNULAR RING" at 11207.23,4004.7 h60
  text "EXTERNAL" at 12939.46,4004.7 h60
  text "1)ALL VIAS ARE TENTED OTHER THAN THERMAL VIAS.." at 6762.38,3901.77 h50
  text "PER" at 11407.23,3886.7 h60
  text "IPC-D-275 CLASS 2 LEVEL C" at 11627.23,3886.7 h60
  text "2)IF NEED COPPER THIEVING CAN BE ADDED BASED ON COPPER BALANCING CALCULATION" at 6762.38,3792.36 h50
  text "MIL, HOLES" at 13115.46,3774.41 h60
  text "+/-" at 12723,3773.7 h60
  text "+/-" at 13577,3773.7 h60
  text "REGISTRATION TOLERANCES:" at 11207.23,3768.7 h60
  text "METAL" at 12407,3768.7 h60
  text "5" at 12983.2,3768.7 h60
  text "3" at 13816.2,3768.7 h60
  text "MIL" at 13932.46,3768.7 h60
  text "AND MAINTAIN 100MIL SPACING FROM ANY FUNCTIONAL CONDUCTOR." at 6850.38,3676.77 h50
  text "3)VENDOR MAY ADJUST SOLDERMASK WHEREVER SOLDERMASK PADS ARE SAME SIZE(1:1)" at 6762.38,3570.77 h50
  text "MATERIAL:" at 11132.46,3559.24 h60
  text "AS PER MANUFACTURING CAPABILITIES AND ALL OTHER SOLDERMASK PADS SHALL NOT BE MODIFIED" at 6850.38,3457.77 h50
  text "FR-4 High Tg" at 12118.9,3418.91 h60
  text "FR-408" at 11553.46,3410.34 h60
  text "X" at 11965.46,3410.34 h60
  text "OTHER" at 13041.46,3410.34 h60
  text "PROVIDED NO ADJACENT COPPER IS EXPOSED AND NO CONFLICT PRODUCED WITH ANY STATED" at 6850.38,3356.77 h50
  text "\"VIA TENTING/COVERING\" REQUIREMENTS." at 6850.38,3263.77 h50
  text "62 MIL (1.6mm) +/-10%" at 11873.56,3247.62 h60
  text "THICKNESS:" at 11207.23,3243.34 h60
  text "X" at 11745.4,3243.34 h60
  text "OTHER" at 13158.46,3243.34 h60
  text "4) SMALL STIRIPS AND MOUNTING HOLES ADDED IN DESIGN" at 6762.78,3091 h50
  text "TOLERANCE:" at 11207.23,3085.34 h60
  text "X" at 12046.53,3085.34 h60
  text "ANSI IPC-6012 TYPE 3 CLASS 2" at 12233.48,3085.34 h60
  text "THOSE ARE DESIGN REQUIREMENT. WHILE SHIPPING BOARDS, PLEASE HAND OVER TO CUSTOMER" at 6908.78,3003 h50
  text "OTHER +/-" at 12233.46,2929.34 h60
  text "BOW & TWIST:" at 11207.23,2772.34 h60
  text "X" at 12046.53,2772.34 h60
  text "ANSI IPC-6012 TYPE 3 CLASS 2" at 12233.48,2772.34 h60
  text "STRIPS DESIGN REQUIREMENT" at 6931,2741 h50
  text "OTHER +/-" at 12233.46,2613.83 h60
  text "DRILLING:" at 11132.46,2475.34 h60
  text "REFERENCE:" at 11207.23,2358.34 h60
  text "X" at 11855.46,2358.34 h60
  text "AS SHOWN" at 12042.46,2358.34 h60
  text "X" at 12756.46,2358.34 h60
  text "NC_DRILL FILES" at 12893.46,2358.34 h60
  text "PTH MIN COPPER THICKNESS:" at 11207.23,2200.34 h60
  text "X" at 12557.46,2200.34 h60
  text "1MIL" at 12694.46,2200.34 h60
  text "OTHER" at 13191.46,2200.34 h60
  text "BOARD FINISH:" at 11132.46,2041.34 h60
  text "SILKSCREEN:" at 11287.68,1923.34 h60
  text "X" at 12236.46,1923.34 h60
  text "TOP" at 12362.46,1923.34 h60
  text "X" at 12746.46,1923.34 h60
  text "BOTTOM" at 12873.46,1923.34 h60
  text "SILKSCREEN COLOR:" at 11287.68,1756.34 h60
  text "X" at 12235.42,1756.34 h60
  text "WHITE" at 12362.46,1756.34 h60
  text "OTHER" at 12873.46,1756.34 h60
  text "X" at 12443.42,1593.14 h60
  text "MATTE" at 12562.64,1592.29 h60
  text "SOLDER RESIST COLOR:" at 11287.68,1586.34 h60
  text "X" at 11855.42,1427.14 h60
  text "GREEN" at 11982.46,1427.14 h60
  text "BLUE" at 12573.46,1427.14 h60
  text "OTHER" at 13111.46,1427.14 h60
  text "IMMERSION GOLD (ENIG)" at 12193.46,1238.62 h60
  text "ENEPIG" at 13531,1235.34 h60
  text "SURFACE FINISH:" at 11132.46,1234.34 h60
  text "X" at 12006.51,1234.34 h60
  text "IMM. TIN/SILVER OR EQUIV" at 11462,1077.34 h60
  text "OTHER" at 12893.46,1077.34 h60
  text "ARRAY/PANEL:" at 11132.46,898.34 h60
  text "X" at 12015.46,896.34 h60
  text "CUT AND TRIM PER MECH LAYER 1" at 12193.46,894.05 h60
  text "N.C. ROUTE" at 12193.46,742.34 h60
  text "V. SCORE" at 13059.46,742.34 h60
  text "CERTIFICATION:" at 11132.46,605.34 h60
  text "MATERIALS AND WORKMANSHIP FOR ALL PCBS" at 11857.46,605.34 h60
  text "TO MEET OR EXCEED THE REQUIREMENTS OF:" at 11857.46,507.34 h60
  text "X" at 11483.96,370.83 h60
  text "ANSI IPC-A-600F CLASS ->" at 11622.96,370.83 h60
  text "X" at 13262.02,370.83 h60
  text "2" at 13380.96,370.84 h60
  text "1" at 13065.96,369.34 h60
  text "3" at 13734.96,369.34 h60
  text "X" at 11486.02,211.34 h60
  text "UL 94V-0" at 11622.96,211.34 h60
  text "X" at 12298.02,211.34 h60
  text "RoHS" at 12434.96,211.34 h60
  text "OTHER" at 13079.36,211.34 h60
  text "PER ORDER" at 13476.42,211.34 h60
  text "ADDITIONAL REQUIREMENTS:" at 11132.46,70.34 h60
  text "MICROSECTION:" at 11207.23,-44.66 h60
  text "YES" at 12112.96,-44.66 h60
  text "REQUIRED" at 12974.46,-200.81 h60
  text "BARE BOARD ELEC. TEST:" at 11207.23,-203.66 h60
  text "NONE" at 12512.96,-203.66 h60
  text "X" at 12847.46,-203.66 h60
  text "PER ORDER" at 13566.46,-203.66 h60
  text "MANUFACTURER'S UL:" at 11207.23,-360.66 h60
  text "RAIL" at 12372.96,-364.95 h60
  text "METAL" at 12864.77,-364.95 h60
  text "X" at 13240,-365.3 h60
  text "SILK" at 13376.46,-364.95 h60
  text "Impedance Control:" at 7928,-682.3 h60
  text "Differential Controlled to 100 Ohms (+/-10%)" at 8052,-823 h60
  text "All 6 mil traces with 12 mil spacing on Layers 1 and 6" at 8538,-970.3 h60
  text "Single Ended Controlled to 50 Ohms (+/-10%)" at 8026,-1158 h60
  text "All 8 mil traces on Layers 1, 3, and 6" at 8531,-1281 h60
  text "Differential Controlled to 90 Ohms (+/-10%)" at 8060,-1481.3 h60
  text "All 5 mil traces with 4.6 mil spacing on Layers 1 and 6" at 8385,-1631.3 h60
  text "All 5 mil traces with 6.1 mil spacing on Layer 3" at 8385,-1771.3 h60
M11 Gerber Information:
  lines w10: -492,-2245.47 6108,-2245.47 ; -492,-2042.13 6110,-2042.13 ; -492,-1838.8 -492,-2448.8 3513,-2448.8 6110,-2448.8 6110,-1838.8 -491.5,-1838.8 -491.5,-2448.8 1084,-2448.8 ; 1973,-2448.8 1973,-1838.8 ; 3240,-2042.13 3240,-1838.8 ; 4080,-2042.13 4080,-1838.8 ; 4702,-2455.3 4702,-2252.47
  text "ALL ARTWORK VIEWED FROM TOP SIDE" at -428.5,-1970.97 h60
  text "BOARD #:" at 2048,-1970.97 h60
  text "REV:" at 3438,-1970.97 h60
  text ".PCB_rev" at 3729.5,-1970.97 h60
  text "SVN REV:" at 4276,-1970.97 h60
  text ".VersionControl_RevNumber" at 4782,-1970.97 h60
  text ".PRJ_Number" at 2557,-1977 h50
  text "LAYER NAME =" at -428.5,-2173.79 h60
  text "TID #:" at 2048,-2174.3 h60
  text "NA" at 2593.5,-2174.3 h60
  text "PLOT NAME =" at -467,-2379 h50
  text "GENERATED    :" at 2050,-2379.64 h60
  text ".Print_Date" at 2919.5,-2379.64 h60
  text ".Print_Time" at 3648.5,-2379.64 h60
  text "TEXAS INSTRUMENTS" at 4913,-2379.64 h60
  text ".plot_File_Name" at 95,-2383 h50
M12 Stackup:
  drawing of 399 lines, arcs and shapes, not listed
  text "Layer" at 10238.28,6403 h50
  text "Name" at 10583.21,6403 h50
  text "Material" at 11361.33,6403 h50
  text "Thickness" at 12081.14,6403 h50
  text "Constant" at 12626,6403 h50
  text "Board Layer Stack" at 13104.22,6403 h50
  text "1" at 10238.28,6303 h50
  text "Top Overlay" at 10583.21,6303 h50
  text "2" at 10238.28,6203 h50
  text "Top Solder" at 10583.21,6203 h50
  text "Solder Resist" at 11361.33,6203 h50
  text "0.70mil" at 12081.14,6203 h50
  text "3.5" at 12626,6203 h50
  text "3" at 10238.28,6103 h50
  text "Top Layer" at 10583.21,6103 h50
  text "Copper" at 11361.33,6103 h50
  text "1.40mil" at 12081.14,6103 h50
  text "4" at 10238.28,6003 h50
  text "Dielectric 1" at 10583.21,6003 h50
  text "FR-4 High Tg" at 11361.33,6003 h50
  text "5.00mil" at 12081.14,6003 h50
  text "4.6" at 12626,6003 h50
  text "5" at 10238.28,5903 h50
  text "GND1" at 10583.21,5903 h50
  text "Copper" at 11361.33,5903 h50
  text "1.40mil" at 12081.14,5903 h50
  text "6" at 10238.28,5803 h50
  text "Dielectric  2" at 10583.21,5803 h50
  text "FR-4 High Tg" at 11361.33,5803 h50
  text "5.00mil" at 12081.14,5803 h50
  text "4.6" at 12626,5803 h50
  text "7" at 10238.28,5703 h50
  text "SIG1" at 10583.21,5703 h50
  text "Copper" at 11361.33,5703 h50
  text "1.40mil" at 12081.14,5703 h50
  text "8" at 10238.28,5603 h50
  text "Dielectric 3" at 10583.21,5603 h50
  text "FR-4 High Tg" at 11361.33,5603 h50
  text "32.00mil" at 12081.14,5603 h50
  text "4.6" at 12626,5603 h50
  text "9" at 10238.28,5503 h50
  text "SIG2" at 10583.21,5503 h50
  text "Copper" at 11361.33,5503 h50
  text "1.40mil" at 12081.14,5503 h50
  text "10" at 10238.28,5403 h50
  text "Dielectric 4" at 10583.21,5403 h50
  text "FR-4 High Tg" at 11361.33,5403 h50
  text "5.00mil" at 12081.14,5403 h50
  text "4.6" at 12626,5403 h50
  text "11" at 10238.28,5303 h50
  text "GND2" at 10583.21,5303 h50
  text "Copper" at 11361.33,5303 h50
  text "1.40mil" at 12081.14,5303 h50
  text "12" at 10238.28,5203 h50
  text "Dielectric 5" at 10583.21,5203 h50
  text "FR-4 High Tg" at 11361.33,5203 h50
  text "5.00mil" at 12081.14,5203 h50
  text "4.6" at 12626,5203 h50
  text "13" at 10238.28,5103 h50
  text "Bottom Layer" at 10583.21,5103 h50
  text "Copper" at 11361.33,5103 h50
  text "1.40mil" at 12081.14,5103 h50
  text "14" at 10238.28,5003 h50
  text "Bottom Solder" at 10583.21,5003 h50
  text "Solder Resist" at 11361.33,5003 h50
  text "0.70mil" at 12081.14,5003 h50
  text "3.5" at 12626,5003 h50
  text "15" at 10238.28,4903 h50
  text "Bottom Overlay" at 10583.21,4903 h50
M13 Component Bodies Top:
  text ".Layer_Name" at 377,-2173.79 h60
M14 Component Bodies Bottom:
  text ".Layer_Name" at 377,-2173.79 h60
M15 Courtyards Top:
  text ".Layer_Name" at 377,-2173.79 h60
M16 Courtyards Bottom:
  text ".Layer_Name" at 377,-2173.79 h60
Drill Drawing:
  drawing of 183 lines, arcs and shapes, not listed
  text "Symbol" at 7000.98,6194 h36
  text "Count" at 7257.12,6194 h36
  text "Hole Size" at 7579.03,6194 h36
  text "Plated" at 8155.86,6194 h36
  text "Hole Tolerance" at 8412,6194 h36
  text "Hole Length" at 8958.84,6194 h36
  text "74" at 7257.12,6119 h30
  text "7.87mil (0.200mm)" at 7579.03,6119 h30
  text "PTH" at 8155.86,6119 h30
  text "+0.00mil/-7.87mil" at 8412,6119 h30
  text "-" at 8958.84,6119 h30
  text "A" at 6985.75,6113.01 h33.33
  text "48" at 7257.12,6044 h30
  text "10.00mil (0.254mm)" at 7579.03,6044 h30
  text "NPTH" at 8155.86,6044 h30
  text "+/-2.00mil" at 8412,6044 h30
  text "-" at 8958.84,6044 h30
  text "43" at 7257.12,5969 h30
  text "10.00mil (0.254mm)" at 7579.03,5969 h30
  text "PTH" at 8155.86,5969 h30
  text "+0.00mil/-10.00mil" at 8412,5969 h30
  text "-" at 8958.84,5969 h30
  text "C" at 6985.75,5963.01 h33.33
  text "967" at 7257.12,5894 h30
  text "12.00mil (0.305mm)" at 7579.03,5894 h30
  text "PTH" at 8155.86,5894 h30
  text "+0.00mil/-12.00mil" at 8412,5894 h30
  text "-" at 8958.84,5894 h30
  text "B" at 6985.75,5888.01 h33.33
  text "2" at 7257.12,5819 h30
  text "12.00mil (0.305mm)" at 7579.03,5819 h30
  text "PTH" at 8155.86,5819 h30
  text "-" at 8958.84,5819 h30
  text "D" at 6985.75,5813.01 h33.33
  text "11" at 7257.12,5744 h30
  text "17.72mil (0.450mm)" at 7579.03,5744 h30
  text "PTH" at 8155.86,5744 h30
  text "+/-3.00mil" at 8412,5744 h30
  text "-" at 8958.84,5744 h30
  text "2" at 7257.12,5669 h30
  text "23.62mil (0.600mm)" at 7579.03,5669 h30
  text "PTH" at 8155.86,5669 h30
  text "+/-3.00mil" at 8412,5669 h30
  text "51.18mil (1.300mm)" at 8958.84,5669 h30
  text "2" at 7257.12,5594 h30
  text "27.56mil (0.700mm)" at 7579.03,5594 h30
  text "PTH" at 8155.86,5594 h30
  text "+/-3.00mil" at 8412,5594 h30
  text "33.47mil (0.850mm)" at 8958.84,5594 h30
  text "8" at 7257.12,5519 h30
  text "35.04mil (0.890mm)" at 7579.03,5519 h30
  text "PTH" at 8155.86,5519 h30
  text "+/-3.00mil" at 8412,5519 h30
  text "-" at 8958.84,5519 h30
  text "12" at 7257.12,5444 h30
  text "35.43mil (0.900mm)" at 7579.03,5444 h30
  text "PTH" at 8155.86,5444 h30
  text "-" at 8958.84,5444 h30
  text "2" at 7257.12,5369 h30
  text "39.37mil (1.000mm)" at 7579.03,5369 h30
  text "PTH" at 8155.86,5369 h30
  text "+/-3.00mil" at 8412,5369 h30
  text "118.11mil (3.000mm)" at 8958.84,5369 h30
  text "1" at 7257.12,5294 h30
  text "39.37mil (1.000mm)" at 7579.03,5294 h30
  text "PTH" at 8155.86,5294 h30
  text "+/-3.00mil" at 8412,5294 h30
  text "137.79mil (3.500mm)" at 8958.84,5294 h30
  text "87" at 7257.12,5219 h30
  text "40.00mil (1.016mm)" at 7579.03,5219 h30
  text "PTH" at 8155.86,5219 h30
  text "+/-3.00mil" at 8412,5219 h30
  text "-" at 8958.84,5219 h30
  text "28" at 7257.12,5144 h30
  text "40.00mil (1.016mm)" at 7579.03,5144 h30
  text "PTH" at 8155.86,5144 h30
  text "-" at 8958.84,5144 h30
  text "6" at 7257.12,5069 h30
  text "51.18mil (1.300mm)" at 7579.03,5069 h30
  text "PTH" at 8155.86,5069 h30
  text "+/-3.00mil" at 8412,5069 h30
  text "-" at 8958.84,5069 h30
  text "2" at 7257.12,4994 h30
  text "61.81mil (1.570mm)" at 7579.03,4994 h30
  text "PTH" at 8155.86,4994 h30
  text "+/-3.00mil" at 8412,4994 h30
  text "-" at 8958.84,4994 h30
  text "16" at 7257.12,4919 h30
  text "106.00mil (2.692mm)" at 7579.03,4919 h30
  text "PTH" at 8155.86,4919 h30
  text "+/-3.00mil" at 8412,4919 h30
  text "-" at 8958.84,4919 h30
  text "8" at 7257.12,4844 h30
  text "125.98mil (3.200mm)" at 7579.03,4844 h30
  text "PTH" at 8155.86,4844 h30
  text "+/-3.00mil" at 8412,4844 h30
  text "-" at 8958.84,4844 h30
  text "2" at 7257.12,4769 h30
  text "128.00mil (3.251mm)" at 7579.03,4769 h30
  text "PTH" at 8155.86,4769 h30
  text "+/-3.00mil" at 8412,4769 h30
  text "-" at 8958.84,4769 h30
  text "1321 Total" at 7257.12,4694 h30
  text "Slot definitions :" at 7000.98,4619.51 h30
  text "Routed Path Length" at 7520.12,4619.51 h30
  text "= Calculated from tool start centre position to tool end centre position." at 8074.26,4619.51 h30
  text "Hole Length" at 7520.12,4567.53 h30
  text "= Routed Path Length + Tool Size = Slot length as defined in the PCB layout" at 7869.32,4567.53 h30
  text ".Layer_Name" at 377,-2173.79 h60
M17 Embedded Cavity:
  text ".Layer_Name" at 480,-2173.79 h60
M18 Embedded Assembly:
  text ".Layer_Name" at 480,-2173.79 h60
M19 Embedded Keepout:
  text ".Layer_Name" at 480,-2173.79 h60
Mechanical 20:
  lines w10: -200,-160 ccw(c-160,-160) -160,-200 6350.55,-200 ccw(c6350.55,-160) 6390.55,-160 6390.55,860.94 6236.02,860.94 cw(c6235.46,893.9) 6202.5,893.34 cw(c6236.53,893.85) 6236.02,927.87 6390.55,927.87 6390.55,6153.7 ccw(c6350.55,6153.7) 6350.55,6193.7 -160,6193.7 ccw(c-160,6153.7) -200,6153.7 -200,-160
Mechanical 21:
  lines w10: 6871.81,2430.09 6591.84,2430.09 cw(c6591.84,2480.09) 6541.84,2480.09 6541.84,2548.09 cw(c6591.84,2548.09) 6591.84,2598.09 6871.81,2598.09 ; 6950.55,2430.09 7301.13,2430.09 ; 6950.55,2598.09 7301,2598.09 ; 7301.13,2430.21 ccw(c7301.13,2480.21) 7351.13,2480.21 7351.13,2548.21 ccw(c7301.13,2548.21) 7301.13,2598.21 ; 7951.65,2430.39 7671.68,2430.39 cw(c7671.68,2480.39) 7621.68,2480.39 7621.68,2548.39 cw(c7671.68,2548.39) 7671.68,2598.39 7951.65,2598.39 ; 8030.39,2430.39 8380.97,2430.39 ; 8030.39,2598.39 8380.84,2598.39 ; 8380.97,2430.52 ccw(c8380.97,2480.52) 8430.97,2480.52 8430.97,2548.52 ccw(c8380.97,2548.52) 8380.97,2598.52

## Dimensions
8500.24,2104.91 to 8500.24,-200.69 on M2 Board Dimensions
7549.13,-150.69 to 8550.24,-150.69 on M2 Board Dimensions
6469.29,-151 to 7470.39,-151 on M2 Board Dimensions
-200,-160 to 6390.55,-160 on M2 Board Dimensions
-160,6193.7 to -160,-200 on M2 Board Dimensions
-200,-1715.3 to 800,-1715.3 on M2 Board Dimensions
